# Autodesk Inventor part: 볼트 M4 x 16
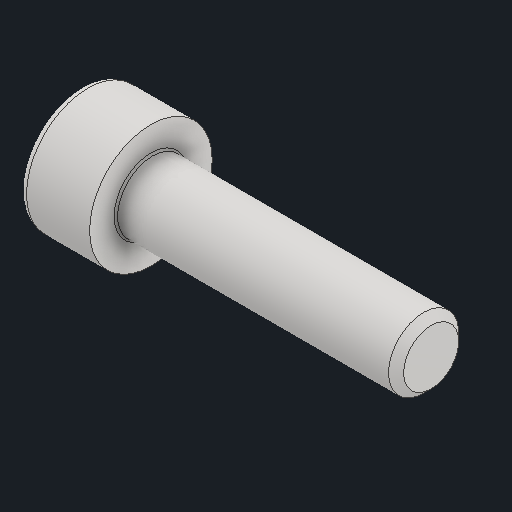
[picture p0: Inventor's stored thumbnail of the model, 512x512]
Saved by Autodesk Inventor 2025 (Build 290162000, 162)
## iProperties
Created: 2025-08
Part Number: 볼트 M4 x 16
Material: 스테인리스강
Description: 6각 소켓 머리 캡 나사
Document SubType Name: Modeling
Designer: infra012
Density: 8.08 g/cm^3
Appearance: 기본값
Author: jhkim
Sending System: Autodesk Inventor 2026
Preprocessor: ST-DEVELOPER v20.1
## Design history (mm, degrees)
sketch "스케치1"
  geometry: 1 further point
  constraints: 1 other
feature "Solid1"
node "솔리드1"
